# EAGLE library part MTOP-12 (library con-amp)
AMP connector
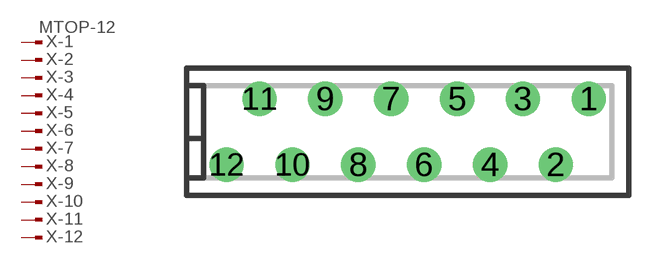
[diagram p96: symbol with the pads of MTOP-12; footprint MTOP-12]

Designator prefix X; gates -1=PIN-MV -2=PIN-M -3=PIN-M -4=PIN-M -5=PIN-M -6=PIN-M -7=PIN-M -8=PIN-M -9=PIN-M -10=PIN-M -11=PIN-M -12=PIN-M

## MTOP-12 (OC_FARNELL: unknown; OC_NEWARK: unknown)  [MTOP-12]
1  -1:1  pas
2  -2:1  pas
3  -3:1  pas
4  -4:1  pas
5  -5:1  pas
6  -6:1  pas
7  -7:1  pas
8  -8:1  pas
9  -9:1  pas
10  -10:1  pas
11  -11:1  pas
12  -12:1  pas

## Footprint MTOP-12 (pad centres in mm)
AMP connector
drill 0.813 round: 1 6.985,1.27; 2 5.715,-1.27; 3 4.445,1.27; 4 3.175,-1.27; 5 1.905,1.27; 6 0.635,-1.27; 7 -0.635,1.27; 8 -1.905,-1.27; 9 -3.175,1.27; 10 -4.445,-1.27; 11 -5.715,1.27; 12 -6.985,-1.27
